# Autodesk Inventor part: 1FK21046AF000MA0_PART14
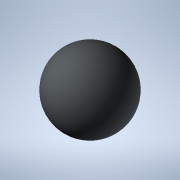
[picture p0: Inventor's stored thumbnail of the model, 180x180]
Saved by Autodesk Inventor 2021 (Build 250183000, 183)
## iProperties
Created: 2025-04
Part Number: 1FK21046AF000MA0_PART14
Material: Generic
Catalog Web Link: www.3dfindit.com
Description: -Servo synchronous motor
Document SubType Name: Modeling
Designer: psAdmin
Mass: 0.137258 g
Surface Area: 1.2868 cm^2
Volume: 0.137258 cm^3
Density: 1 g/cm^3
Appearance: PSOLRGB-212-217-219
Category: PARTsolutions
Title: 1FK21046AF000MA0_PART14
Author: Cadenas PARTsolutions
Comments: Servo synchronous motor
Sending System: PARTsolutions
Preprocessor: ST-DEVELOPER v19.3
PSOL_IDENT_0: {$CADENAS_DATA/23d-libs/siemens_ag/_cat_/1c/1f/1fk21046af000ma0.prj},216 {VTYP=3D},{NB=1FK21046AF000
PSOL_IDENT_1: MA0_PART14},{LINA=1FK21046AF000MA0_PART14},{NN=1FK21046AF000MA0_PART14},{NOPRJ=TRUE},{DATE=19.08.202
PSOL_IDENT_2: 5 14:00:28},{GEOMDATE=30.07.2025 02:02:08},{VERSION=},{LINEID=10},{WBVAR=},{WBNUMERIC=}  {NB=1FK2104
PSOL_IDENT_3: 6AF000MA0_PART14},{LINA=1FK21046AF000MA0_PART14},{KT=DUMMY},{PREVIEW=../../../_pool_/cb/72/p_d211_xx
PSOL_IDENT_4: _00434j.png},{DESCSHORT=SIMOTICS S-1FK2 HD, SINAMICS S210 3AC 400V-480V, 3.2 Nm, 3000 rpm},{DESCLONG=
PSOL_IDENT_5: SIMOTICS S-1FK2 HD servo motor M0=3.2 Nm; PN = 1 kW at nN=3000 rpm (380-480 V); PN = 0.5 kW at nN=15
PSOL_IDENT_6: 00 rpm (200-240 V); degree of protection IP64; cylindrical shaft D19x40mm; absolute encoder 22-bit +
PSOL_IDENT_7: 12-bit multiturn (encoder AM22DQC); with OCC interface; plug size M17, rotatable; SIMOTICS S-1FK2 s
PSOL_IDENT_8: ervomotorfor a wide range of uses in industrial environments. SIMOTICS S‑1FK2 servomotors are compac
PSOL_IDENT_9: t synchronous motors with a high dynamic performance that set themselves apart as a result of their
PSOL_IDENT_10: high power density, degree of protection and overload capability. The motors are available in two va
PSOL_IDENT_11: riants: as High Dynamic variant (highest dynamic performance as a result of the low intrinsic moment
PSOL_IDENT_12: of inertia for applications demanding a high dynamic performance with low moved masses) - and as Co
PSOL_IDENT_13: mpact variant (precise and stable closed-loop control for medium up to large moved masses as a resul
PSOL_IDENT_14: t of a medium intrinsic moment of inertia). SIMOTICSS‑1FK2 servomotors fully exploit their strengths
PSOL_IDENT_15: in a system with the SINAMICSS210 frequency converter and simple connection using the one cable con
PSOL_IDENT_16: nection (OCC). Advantages include the short control and positioning times, fast and precise correcti
PSOL_IDENT_17: on of disturbing quantities as well as stable control with a high dynamic performance. The servo mot
PSOL_IDENT_18: ors can be configured to address a wide range of requirements. For example with and without holding
PSOL_IDENT_19: brake, IP64 or IP65 degree of protection, singleturn or multiturn absolute encoders - to name just a
PSOL_IDENT_20: few. Further, the servomotors are available in different shaft heights extending from 20 to 100. A
PSOL_IDENT_21: shaft sealing ring is available to achieve an IP65 degree of protection and for subsequent mounting
PSOL_IDENT_22: at the motor or as spare part. SIMOTICS - the optimum motor for each and every motion control applic
PSOL_IDENT_23: ation.},{INTNO=195125049666},{SUPPLIERALTNO=1FK2104-6AF00-0MA0},{MANUID=1FK21046AF000MA0},{MANUNAME=
PSOL_IDENT_24: Siemens},{MANUTYPEDESC=Synchronous motor 1FK2-HD 3.2 NM},{AAU732=SIMOTICS},{AAO057=S-1FK2},{AAU734=S
PSOL_IDENT_25: IMOTICS S-1FK2 HD servo motor M0=3.2 Nm; PN = 1 kW at nN=3000 rpm (380-480 V); PN = 0.5 kW at nN=150
PSOL_IDENT_26: 0 rpm (200-240 V); degree of protection IP64; cylindrical shaft D19x40mm; absolute encoder 22-bit +
PSOL_IDENT_27: 12-bit multiturn (encoder AM22DQC); with OCC interface; plug size M17, rotatable;},{AAW338=Synchrono
PSOL_IDENT_28: us motor 1FK2-HD 3.2 NM},{AAO742=SIMOTICS},{AAO663=4042948694374},{NOCUPEROU=1},{PRICEQUANTITY=1},{Q
PSOL_IDENT_29: UANTITYMIN=1},{QUANTITYINT=1},{CTN=85015220},{COO=DE},{AAO676=1FK2104-6AF00-0MA0},{AAO677=Siemens AG
PSOL_IDENT_30: },{ORDERUNIT=C62},{CONTENTUNIT=C62}
NB: 1FK21046AF000MA0_PART14
NT: Servo synchronous motor
NBSYN: $MANUID._PART14
LINA: 1FK21046AF000MA0_PART14
CATALOG: SIEMENS
PREVIEW: ../../../_pool_/cb/72/p_d211_xx_00434j.png
DESCSHORT: SIMOTICS S-1FK2 HD, SINAMICS S210 3AC 400V-480V, 3.2 Nm, 3000 rpm
DESCLONG: SIMOTICS S-1FK2 HD servo motor M0=3.2 Nm; PN = 1 kW at nN=3000 rpm (380-480 V); PN = 0.5 kW at nN=1500 rpm (200-240 V); degree of protection IP64; cylindrical s
INTNO: 195125049666
SUPPLIERALTNO: 1FK2104-6AF00-0MA0
MANUID: 1FK21046AF000MA0
MANUNAME: Siemens
MANUTYPEDESC: Synchronous motor 1FK2-HD 3.2 NM
AAU732: SIMOTICS
AAO057: S-1FK2
AAU734: SIMOTICS S-1FK2 HD servo motor M0=3.2 Nm; PN = 1 kW at nN=3000 rpm (380-480 V); PN = 0.5 kW at nN=1500 rpm (200-240 V); degree of protection IP64; cylindrical s
AAW338: Synchronous motor 1FK2-HD 3.2 NM
AAO742: SIMOTICS
AAO663: 4042948694374.0
NOCUPEROU: 1
PRICEQUANTITY: 1
QUANTITYMIN: 1
QUANTITYINT: 1
CTN: 85015220
COO: DE
ARTICLENO: 1FK21046AF000MA0_PART14
BOMINFO: 1FK21046AF000MA0_PART14
CREATOR: CADENAS GmbH
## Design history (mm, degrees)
feature "2025_04_17_15_39_11_0412"
body "Solid1"
